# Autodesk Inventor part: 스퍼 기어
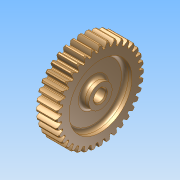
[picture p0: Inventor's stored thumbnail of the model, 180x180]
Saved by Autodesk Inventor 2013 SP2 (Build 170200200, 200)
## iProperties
Created: 2025-10
Part Number: 스퍼 기어
Material: Generic
Document SubType Name: Modeling
Designer: a
Density: 1 g/cm^3
변환 표준: STEP AP214IS
전처리기: Build: 200, Release: 2013 SP2 Update 6 - Date: Thu 07/17/2014
전송 단위: 밀리미터
불확실성: 0.01
Author: a
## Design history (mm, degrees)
node "스퍼 기어1"
node "솔리드1"
node "기준1"
